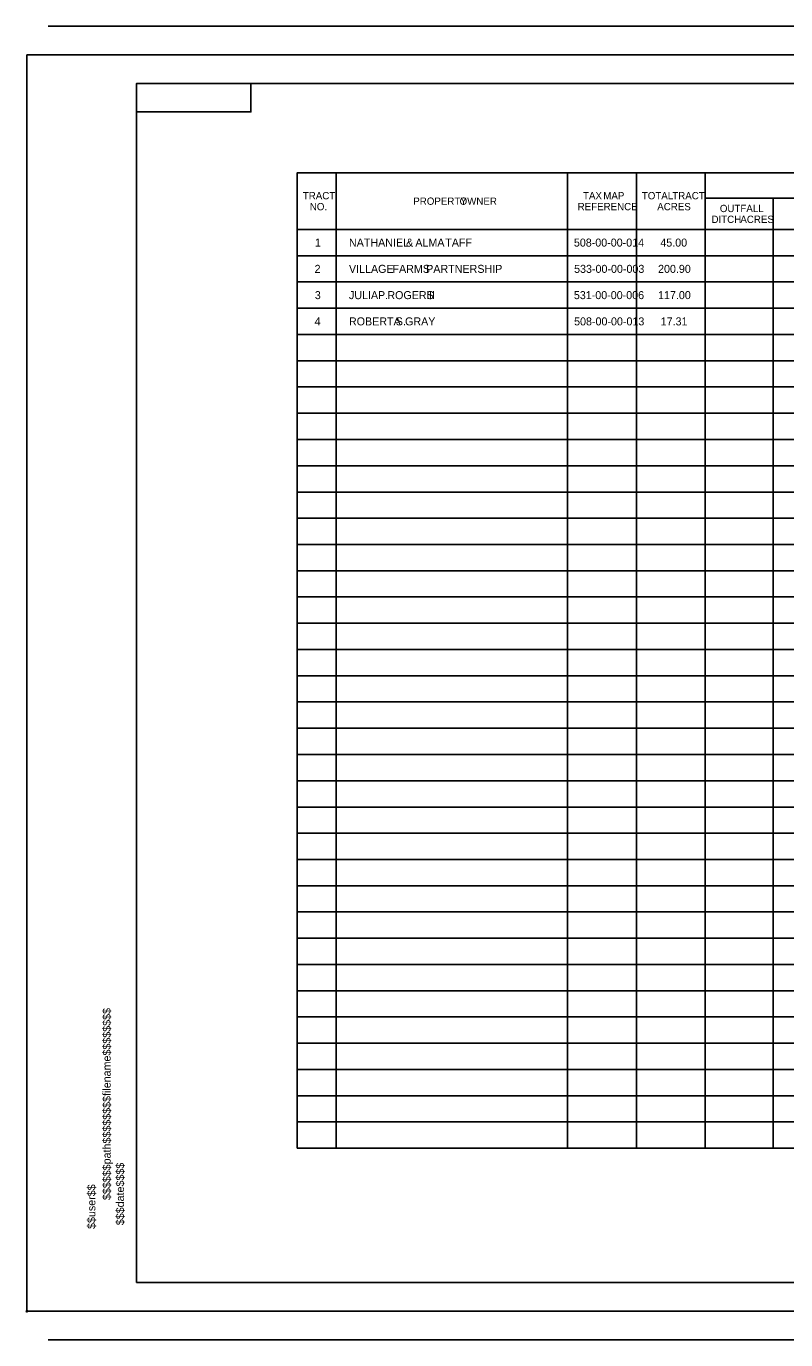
# Model space of a CAD drawing. Extents: x -19 to 1777, y -25 to 1125.
# Drawn here: x -19 to 646, y -25 to 1125 of the extents above; entities that cross this region are included whole.
import ezdxf

# ---------------------------------------------------------------- set-up
doc = ezdxf.new("R2010")
doc.units = 0
for name, color, linetype in [('RD_SHT_Bndy', 7, 'Continuous'), ('RD_SHT_ID', 7, 'Continuous'), ('RD_SHT_Iplotshp', 7, 'Continuous'), ('RD_SHT_MjGrid', 7, 'Continuous'), ('RD_SHT_Snap', 7, 'Continuous'), ('RD_TX_Misc1', 7, 'Continuous'), ('RD_TX_RW', 7, 'Continuous')]:
    doc.layers.add(name, color=color, linetype=linetype)

msp = doc.modelspace()

# ---------------------------------------------------------------- linework, layer by layer
at = {"layer": 'RD_SHT_Bndy'}
for p, q in [((0, 1125), (1760, 1125)), ((0, 1100), (1760, 1100)), ((77.4, 1075), (77.4, 175)), ((1752.4, 1075), (77.4, 1075)), ((77.4, 175), (77.4, 25.1)), ((77.4, 25), (1752.4, 25)), ((0, 0), (1760, 0)), ((0, -25), (1760, -25))]:
    msp.add_line(p, q, dxfattribs=at)
for points in [[(77.4, 1050), (77.4, 1075), (177.4, 1075), (177.4, 1050)], [(218, 142.7), (1560.9, 142.7), (1560.9, 996.8), (218, 996.8)]]:
    msp.add_lwpolyline(points, close=True, dxfattribs=at)
at = {"layer": 'RD_SHT_Iplotshp'}
msp.add_lwpolyline([(-18.6, 1100), (1777.4, 1100), (1777.4, 0), (-18.6, 0)], close=True, dxfattribs=at)
at = {"layer": 'RD_SHT_MjGrid'}
for p, q in [((218, 996.8), (1560.9, 996.8)), ((218, 142.7), (218, 996.8)), ((252.2, 142.7), (252.2, 996.8)), ((454.7, 142.7), (454.7, 996.8)), ((514.9, 142.7), (514.9, 996.8)), ((575.2, 142.7), (575.2, 996.8)), ((575.2, 974.4), (813.7, 974.4)), ((634.8, 142.7), (634.8, 974.4)), ((218, 947.1), (1560.9, 947.1)), ((218, 924.1), (1560.9, 924.1)), ((218, 901.1), (1560.9, 901.1)), ((218, 878.1), (1560.9, 878.1)), ((218, 855.1), (1560.9, 855.1)), ((218, 832.1), (1560.9, 832.1)), ((218, 809.2), (1560.9, 809.2)), ((218, 786.2), (1560.9, 786.2)), ((218, 763.2), (1560.9, 763.2)), ((218, 740.2), (1560.9, 740.2)), ((218, 717.2), (1560.9, 717.2)), ((218, 694.3), (1560.9, 694.3)), ((218, 671.3), (1560.9, 671.3)), ((218, 648.3), (1560.9, 648.3)), ((218, 625.3), (1560.9, 625.3)), ((218, 602.3), (1560.9, 602.3)), ((218, 579.3), (1560.9, 579.3)), ((218, 556.4), (1560.9, 556.4)), ((218, 533.4), (1560.9, 533.4)), ((218, 510.4), (1560.9, 510.4)), ((218, 487.4), (1560.9, 487.4)), ((218, 464.4), (1560.9, 464.4)), ((218, 441.4), (1560.9, 441.4)), ((218, 418.5), (1560.9, 418.5)), ((218, 395.5), (1560.9, 395.5)), ((218, 372.5), (1560.9, 372.5)), ((218, 349.5), (1560.9, 349.5)), ((218, 326.5), (1560.9, 326.5)), ((218, 303.6), (1560.9, 303.6)), ((218, 280.6), (1560.9, 280.6)), ((218, 257.6), (1560.9, 257.6)), ((218, 234.6), (1560.9, 234.6)), ((218, 211.6), (1560.9, 211.6)), ((218, 188.6), (1560.9, 188.6)), ((218, 165.7), (1560.9, 165.7)), ((218, 142.7), (1560.9, 142.7))]:
    msp.add_line(p, q, dxfattribs=at)
at = {"layer": 'RD_SHT_Snap'}
msp.add_line((-18.6, 0), (-18.6, 1100), dxfattribs=at)
msp.add_circle((-18.6, 0), 0.607, dxfattribs=at)
at = {"layer": 'RD_TX_Misc1'}
msp.add_line((218, 996.8), (218, 996.8), dxfattribs=at)

# ---------------------------------------------------------------- texts
at = {"layer": 'RD_SHT_ID'}
for s, p in [('$$$$$$path$$$$$$$$filename$$$$$$$$', (54.7, 97.3)), ('$$$date$$$$', (66.4, 75.3)), ('$$user$$', (41.3, 72))]:
    msp.add_text(s, height=7, rotation=90, dxfattribs=at).set_placement(p)
at = {"layer": 'RD_TX_RW'}
for s, height, p in [('TRACT', 6.37, (222.9, 973.5)), ('TAX', 6.37, (468.2, 973.5)), (' MAP', 6.37, (483.6, 973.5)), ('TOTAL', 6.37, (519.7, 973.5)), (' TRACT', 6.37, (544, 973.5)), ('NO.', 6.37, (229, 963.9)), ('PROPERTY', 6.37, (319.6, 968.7)), (' OWNER', 6.37, (357.8, 968.7)), ('REFERENCE', 6.37, (463.5, 963.9)), ('ACRES', 6.37, (533.2, 963.9)), ('OUTFALL', 6.37, (588, 962.3)), ('DITCH', 6.37, (580.7, 952.8)), (' ACRES', 6.37, (603.6, 952.8)), ('1', 7.01, (233.5, 932.1)), ('NATHANIEL', 7.01, (263.3, 932.1)), (' &', 7.01, (310.7, 932.1)), (' ALMA', 7.01, (318.8, 932.1)), (' TAFF', 7.01, (345, 932.1)), ('508-00-00-014', 7.008, (460.2, 932.1)), ('45.00', 7.01, (535.9, 932.1)), ('2', 7.01, (233.2, 909.1)), ('VILLAGE', 7.01, (263.3, 909.1)), (' FARMS', 7.01, (298.8, 909.1)), (' PARTNERSHIP', 7.008, (328.3, 909.1)), ('533-00-00-003', 7.008, (460.4, 909.1)), ('200.90', 7.01, (533.9, 909.1)), ('3', 7.01, (233.4, 886.1)), ('JULIA', 7.01, (263.3, 886.1)), (' P.', 7.01, (286.1, 886.1)), (' ROGERS', 7.01, (294.3, 886.1)), (' III', 7.01, (328.3, 886.1)), ('531-00-00-006', 7.008, (460.2, 886.1)), ('117.00', 7.01, (533.9, 886.1)), ('4', 7.01, (233.2, 863.1)), ('ROBERTA', 7.01, (263.3, 863.1)), (' S.', 7.01, (301.7, 863.1)), (' GRAY', 7.01, (309.8, 863.1)), ('508-00-00-013', 7.008, (460.4, 863.1)), ('17.31', 7.01, (536.2, 863.1))]:
    msp.add_text(s, height=height, dxfattribs=at).set_placement(p)

doc.saveas('drawing.dxf')
